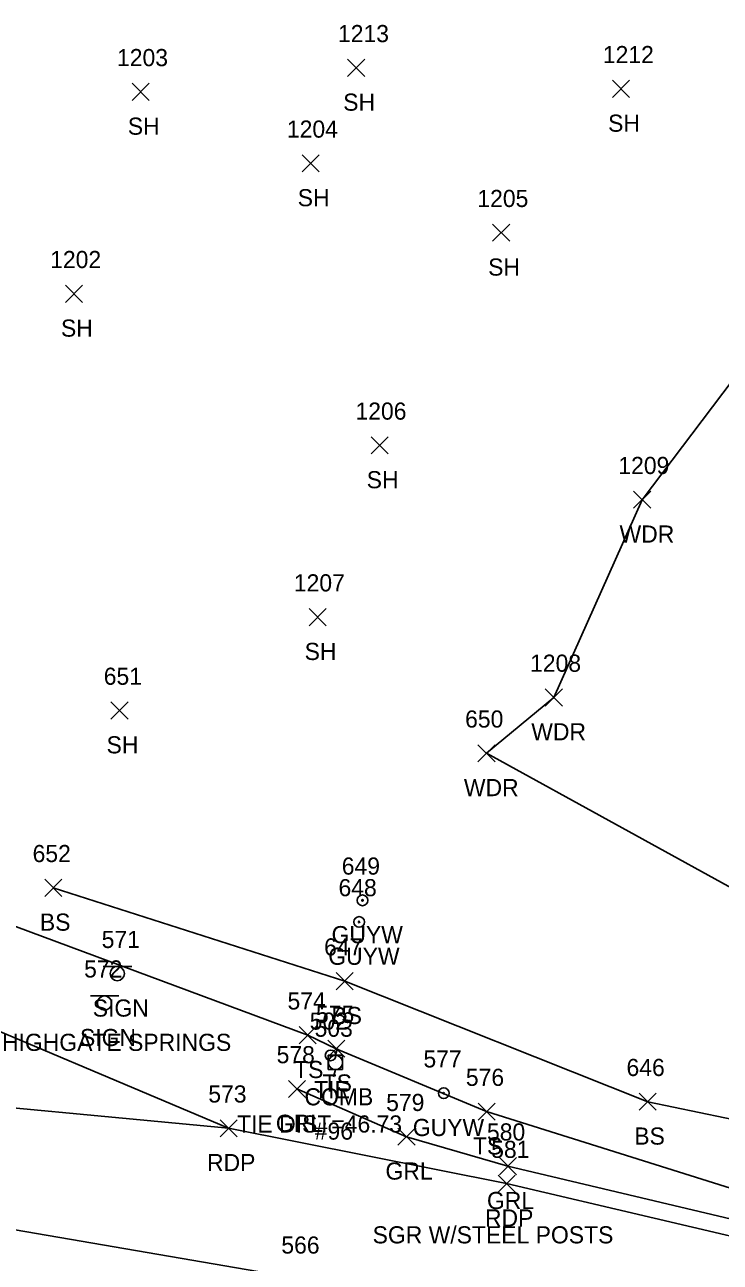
# Model space of a CAD drawing. Extents: x 1485624 to 1495982, y 886445 to 890805.
# Drawn here: x 1495626.2 to 1495707.4, y 890605.4 to 890749.8 of the extents above; entities that cross this region are included whole.
import ezdxf

# ---------------------------------------------------------------- set-up
doc = ezdxf.new("R2010")
doc.units = 0
for name, color, linetype in [('C_A', 7, 'Continuous'), ('C_C', 7, 'Continuous'), ('C_I', 7, 'Continuous'), ('CBP', 7, 'Continuous'), ('L_A', 7, 'Continuous'), ('L_I', 7, 'Continuous'), ('L_TIC', 7, 'Continuous'), ('LAWA', 7, 'Continuous'), ('LELB', 7, 'Continuous'), ('P_A', 7, 'Continuous'), ('P_I', 7, 'Continuous'), ('P_TIC', 7, 'Continuous'), ('PET', 7, 'Continuous'), ('PRC', 7, 'Continuous'), ('R_A', 7, 'Continuous'), ('R_C', 7, 'Continuous'), ('R_I', 7, 'Continuous'), ('R_TIC', 7, 'Continuous'), ('RGR', 7, 'Continuous'), ('S_A', 7, 'Continuous'), ('S_C', 7, 'Continuous'), ('S_I', 7, 'Continuous'), ('SSGN', 7, 'Continuous'), ('U_A', 7, 'Continuous'), ('U_C', 7, 'Continuous'), ('U_I', 7, 'Continuous'), ('UP', 7, 'Continuous'), ('UPGW', 7, 'Continuous')]:
    doc.layers.add(name, color=color, linetype=linetype)

msp = doc.modelspace()

# ---------------------------------------------------------------- linework, layer by layer
at = {"layer": 'CBP'}
for radius in [0.625, 0.0833]:
    msp.add_circle((1495661.92, 890629.56), radius, dxfattribs=at)
at = {"layer": 'L_TIC'}
for points in [[(1495663.9, 890743.73), (1495665.9, 890745.73)], [(1495665.9, 890743.73), (1495663.9, 890745.73)], [(1495638.77, 890740.93), (1495640.77, 890742.93)], [(1495640.77, 890740.93), (1495638.77, 890742.93)], [(1495694.8, 890741.28), (1495696.8, 890743.28)], [(1495696.8, 890741.28), (1495694.8, 890743.28)], [(1495658.59, 890732.59), (1495660.59, 890734.59)], [(1495660.59, 890732.59), (1495658.59, 890734.59)], [(1495680.81, 890724.5), (1495682.81, 890726.5)], [(1495682.81, 890724.5), (1495680.81, 890726.5)], [(1495630.98, 890717.38), (1495632.98, 890719.38)], [(1495632.98, 890717.38), (1495630.98, 890719.38)], [(1495666.64, 890699.7), (1495668.64, 890701.7)], [(1495668.64, 890699.7), (1495666.64, 890701.7)], [(1495697.27, 890693.36), (1495699.27, 890695.36)], [(1495699.27, 890693.36), (1495697.27, 890695.36)], [(1495659.4, 890679.67), (1495661.4, 890681.67)], [(1495661.4, 890679.67), (1495659.4, 890681.67)], [(1495686.97, 890670.3), (1495688.97, 890672.3)], [(1495688.97, 890670.3), (1495686.97, 890672.3)], [(1495636.29, 890668.78), (1495638.29, 890670.78)], [(1495638.29, 890668.78), (1495636.29, 890670.78)], [(1495679.11, 890663.79), (1495681.11, 890665.79)], [(1495681.11, 890663.79), (1495679.11, 890665.79)], [(1495628.56, 890648.1), (1495630.56, 890650.1)], [(1495630.56, 890648.1), (1495628.56, 890650.1)], [(1495662.57, 890637.21), (1495664.57, 890639.21)], [(1495664.57, 890637.21), (1495662.57, 890639.21)], [(1495658.25, 890630.91), (1495660.25, 890632.91)], [(1495660.25, 890630.91), (1495658.25, 890632.91)], [(1495661.58, 890629.34), (1495663.58, 890631.34)], [(1495663.58, 890629.34), (1495661.58, 890631.34)], [(1495697.91, 890623.15), (1495699.91, 890625.15)], [(1495699.91, 890623.15), (1495697.91, 890625.15)], [(1495679.12, 890622), (1495681.12, 890624)], [(1495681.12, 890622), (1495679.12, 890624)]]:
    msp.add_lwpolyline(points, dxfattribs=at)
at = {"layer": 'LAWA'}
for points in [[(1495687.97, 890671.3), (1495698.27, 890694.36), (1495713.49, 890714.44), (1495722.08, 890739.54)], [(1495680.11, 890664.79), (1495687.97, 890671.3)], [(1495871.71, 890600.37), (1495858, 890600.35), (1495826.66, 890611.45), (1495806.15, 890618.61), (1495786.69, 890637.23), (1495776.7, 890630.96), (1495766.77, 890633.56), (1495731.4, 890630.07), (1495727.41, 890643.49), (1495711.78, 890647.37), (1495680.11, 890664.79)]]:
    msp.add_lwpolyline(points, dxfattribs=at)
at = {"layer": 'LELB'}
for points in [[(1495769.4, 890642.32), (1495731.4, 890630.07), (1495716.89, 890620.39), (1495698.91, 890624.15), (1495663.57, 890638.21), (1495629.56, 890649.1)], [(1495617.51, 890647.42), (1495659.25, 890631.91), (1495662.58, 890630.34), (1495680.12, 890623), (1495718.11, 890611.07), (1495750.98, 890602.51), (1495783.18, 890591.68), (1495810.94, 890582.07), (1495845.91, 890568.15), (1495889.08, 890548.91)]]:
    msp.add_lwpolyline(points, dxfattribs=at)
at = {"layer": 'P_TIC'}
for points in [[(1495649.02, 890620.06), (1495651.02, 890622.06)], [(1495651.02, 890620.06), (1495649.02, 890622.06)], [(1495649.02, 890620.06), (1495651.02, 890622.06)], [(1495651.02, 890620.06), (1495649.02, 890622.06)], [(1495681.45, 890613.6), (1495683.45, 890615.6)], [(1495683.45, 890613.6), (1495681.45, 890615.6)]]:
    msp.add_lwpolyline(points, dxfattribs=at)
at = {"layer": 'PET'}
for points in [[(1495613.51, 890636.45), (1495650.02, 890621.06)], [(1495609.58, 890624.88), (1495650.02, 890621.06), (1495682.45, 890614.6), (1495716.9, 890606.52), (1495749.59, 890597.76), (1495779.95, 890588.14), (1495810.5, 890576.96), (1495843, 890563.53), (1495882.78, 890545.01)]]:
    msp.add_lwpolyline(points, dxfattribs=at)
at = {"layer": 'PRC'}
msp.add_lwpolyline([(1495865.85, 890538.25), (1495835.89, 890551.78), (1495804.87, 890564.57), (1495770.54, 890576.59), (1495737.23, 890586.26), (1495702.08, 890594.9), (1495658.63, 890603.44), (1495614.66, 890611.01)], dxfattribs=at)
at = {"layer": 'R_TIC'}
for points in [[(1495656.99, 890624.64), (1495658.99, 890626.64)], [(1495658.99, 890624.64), (1495656.99, 890626.64)], [(1495669.77, 890619.07), (1495671.77, 890621.07)], [(1495671.77, 890619.07), (1495669.77, 890621.07)], [(1495681.61, 890615.63), (1495683.61, 890617.63)], [(1495683.61, 890615.63), (1495681.61, 890617.63)]]:
    msp.add_lwpolyline(points, dxfattribs=at)
at = {"layer": 'RGR'}
msp.add_lwpolyline([(1495657.99, 890625.64), (1495670.77, 890620.07), (1495682.61, 890616.63), (1495717.55, 890608.37), (1495750.4, 890599.5), (1495781.03, 890589.57), (1495810.95, 890578.47), (1495843.97, 890564.67), (1495884.04, 890546.25), (1495911.23, 890532.9), (1495928.25, 890525.82), (1495941.85, 890522.12)], dxfattribs=at)
at = {"layer": 'SSGN'}
for p, q in [((1495635.38, 890639.93), (1495638.72, 890639.93)), ((1495637.03, 890639.1), (1495637.03, 890639.1)), ((1495633.89, 890636.49), (1495637.22, 890636.49)), ((1495635.54, 890635.66), (1495635.54, 890635.66))]:
    msp.add_line(p, q, dxfattribs=at)
for centre in [(1495637.03, 890639.1), (1495635.54, 890635.66)]:
    msp.add_circle(centre, 0.833, dxfattribs=at)
at = {"layer": 'UP'}
for p, q in [((1495662.74, 890630.4), (1495662.49, 890629.57)), ((1495661.65, 890627.9), (1495661.65, 890629.57)), ((1495661.65, 890629.57), (1495663.32, 890629.57)), ((1495663.32, 890629.57), (1495663.32, 890627.9)), ((1495663.32, 890627.9), (1495661.65, 890627.9)), ((1495662.24, 890627.07), (1495662.49, 890627.9)), ((1495662.49, 890628.73), (1495662.49, 890628.73))]:
    msp.add_line(p, q, dxfattribs=at)
msp.add_circle((1495662.49, 890628.73), 0.833, dxfattribs=at)
at = {"layer": 'UPGW'}
for centre, radius in [((1495665.64, 890647.64), 0.625), ((1495665.64, 890647.64), 0.0833), ((1495665.25, 890645.12), 0.625), ((1495665.25, 890645.12), 0.0833), ((1495675.12, 890625.15), 0.625), ((1495675.12, 890625.15), 0.0833)]:
    msp.add_circle(centre, radius, dxfattribs=at)

# ---------------------------------------------------------------- texts
at = {"layer": 'C_A'}
msp.add_text('TIE', height=2, dxfattribs=at).set_placement((1495660, 890624.56))
at = {"layer": 'C_C'}
msp.add_text('TIE DIST=46.73', height=2, dxfattribs=at).set_placement((1495651.01, 890620.56))
at = {"layer": 'C_I'}
msp.add_text('502', height=2, dxfattribs=at).set_placement((1495659.48, 890632.56))
at = {"layer": 'L_A'}
for s, p in [('SH', (1495663.39, 890739.73)), ('SH', (1495638.26, 890736.93)), ('SH', (1495694.29, 890737.28)), ('SH', (1495658.08, 890728.59)), ('SH', (1495680.3, 890720.5)), ('SH', (1495630.46, 890713.38)), ('SH', (1495666.13, 890695.7)), ('WDR', (1495695.63, 890689.36)), ('SH', (1495658.89, 890675.67)), ('WDR', (1495685.33, 890666.3)), ('SH', (1495635.78, 890664.78)), ('WDR', (1495677.47, 890659.79)), ('BS', (1495628, 890644.1)), ('BS', (1495662.01, 890633.21)), ('TS', (1495657.66, 890626.91)), ('TS', (1495660.99, 890625.34)), ('BS', (1495697.35, 890619.15)), ('TS', (1495678.53, 890618))]:
    msp.add_text(s, height=2, dxfattribs=at).set_placement(p)
at = {"layer": 'L_I'}
for s, p in [('1213', (1495662.78, 890747.73)), ('1212', (1495693.68, 890745.28)), ('1203', (1495637, 890744.93)), ('1204', (1495656.82, 890736.59)), ('1205', (1495679.04, 890728.5)), ('1202', (1495629.2, 890721.38)), ('1206', (1495664.82, 890703.7)), ('1209', (1495695.49, 890697.36)), ('1207', (1495657.63, 890683.67)), ('1208', (1495685.19, 890674.3)), ('651', (1495635.45, 890672.78)), ('650', (1495677.61, 890667.79)), ('652', (1495627.15, 890652.1)), ('647', (1495661.16, 890641.21)), ('574', (1495656.89, 890634.91)), ('575', (1495660.21, 890633.34)), ('646', (1495696.44, 890627.15)), ('576', (1495677.7, 890626))]:
    msp.add_text(s, height=2, dxfattribs=at).set_placement(p)
at = {"layer": 'P_A'}
for p in [(1495647.5, 890616.06), (1495647.5, 890616.06), (1495679.93, 890609.6)]:
    msp.add_text('RDP', height=2, dxfattribs=at).set_placement(p)
at = {"layer": 'P_I'}
for s, p in [('573', (1495647.65, 890624.06)), ('573', (1495647.65, 890624.06)), ('581', (1495680.65, 890617.6)), ('566', (1495656.17, 890606.44))]:
    msp.add_text(s, height=2, dxfattribs=at).set_placement(p)
at = {"layer": 'R_A'}
for p in [(1495655.53, 890620.64), (1495668.32, 890615.07), (1495680.16, 890611.63)]:
    msp.add_text('GRL', height=2, dxfattribs=at).set_placement(p)
at = {"layer": 'R_C'}
msp.add_text('SGR W/STEEL POSTS', height=2, dxfattribs=at).set_placement((1495666.82, 890607.63))
at = {"layer": 'R_I'}
for s, p in [('578', (1495655.62, 890628.64)), ('579', (1495668.4, 890623.07)), ('580', (1495680.16, 890619.63))]:
    msp.add_text(s, height=2, dxfattribs=at).set_placement(p)
at = {"layer": 'S_A'}
for p in [(1495634.17, 890634.08), (1495632.68, 890630.64)]:
    msp.add_text('SIGN', height=2, dxfattribs=at).set_placement(p)
at = {"layer": 'S_C'}
msp.add_text('HIGHGATE SPRINGS', height=2, dxfattribs=at).set_placement((1495623.58, 890630.08))
at = {"layer": 'S_I'}
for s, p in [('571', (1495635.21, 890642.08)), ('572', (1495633.16, 890638.64))]:
    msp.add_text(s, height=2, dxfattribs=at).set_placement(p)
at = {"layer": 'U_A'}
for s, p in [('GUYW', (1495662.03, 890642.64)), ('GUYW', (1495661.65, 890640.12)), ('COMB', (1495658.87, 890623.73)), ('GUYW', (1495671.51, 890620.15))]:
    msp.add_text(s, height=2, dxfattribs=at).set_placement(p)
at = {"layer": 'U_C'}
msp.add_text('#96', height=2, dxfattribs=at).set_placement((1495660.07, 890619.73))
at = {"layer": 'U_I'}
for s, p in [('649', (1495663.22, 890650.64)), ('648', (1495662.84, 890648.12)), ('503', (1495660.05, 890631.73)), ('577', (1495672.75, 890628.15))]:
    msp.add_text(s, height=2, dxfattribs=at).set_placement(p)

doc.saveas('drawing.dxf')
